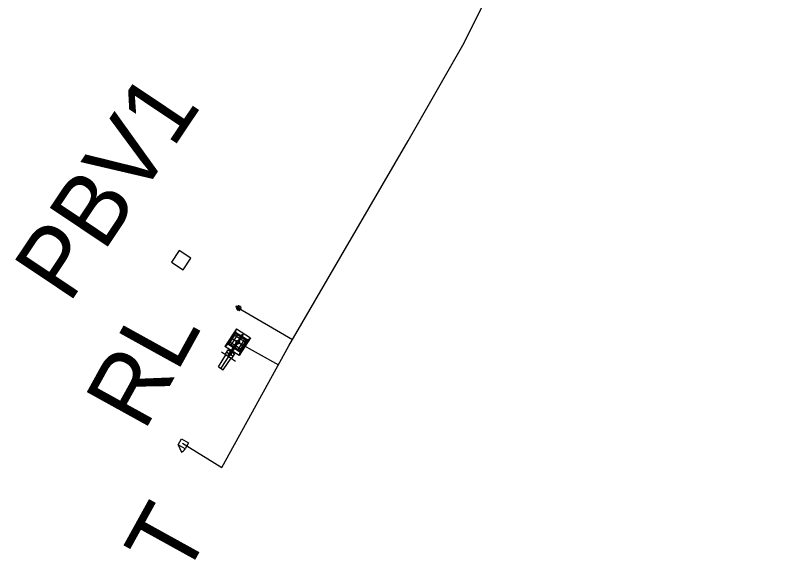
# Model space of a CAD drawing. Extents: x -717079 to -715675, y -957336 to -955099.
# Drawn here: x -715995.85 to -715968.61, y -955365.79 to -955346.3 of the extents above; entities that cross this region are included whole.
import ezdxf

# ---------------------------------------------------------------- set-up
doc = ezdxf.new("R2010")
doc.units = 0
doc.layers.add('TZ_ostatní', color=7, linetype='Continuous')

msp = doc.modelspace()

# ---------------------------------------------------------------- linework, layer by layer
at = {"layer": 'TZ_ostatní'}
for p, q in [((-715989.979, -955354.719), (-715990.252, -955355.138)), ((-715989.56, -955354.992), (-715989.979, -955354.719)), ((-715989.833, -955355.411), (-715989.56, -955354.992)), ((-715990.252, -955355.138), (-715989.833, -955355.411)), ((-715987.942, -955356.707), (-715987.953, -955356.724)), ((-715987.953, -955356.724), (-715987.902, -955356.756)), ((-715987.947, -955356.715), (-715987.788, -955356.819)), ((-715987.891, -955356.74), (-715987.942, -955356.707)), ((-715987.864, -955356.698), (-715987.93, -955356.798)), ((-715987.889, -955356.855), (-715987.796, -955356.712)), ((-715987.82, -955356.721), (-715987.857, -955356.696)), ((-715987.81, -955356.715), (-715987.813, -955356.719)), ((-715987.81, -955356.715), (-715987.793, -955356.726)), ((-715987.793, -955356.726), (-715987.796, -955356.73)), ((-715987.757, -955356.762), (-715987.794, -955356.737)), ((-715987.891, -955356.83), (-715987.928, -955356.805)), ((-715987.892, -955356.841), (-715987.889, -955356.837)), ((-715987.892, -955356.841), (-715987.875, -955356.852)), ((-715987.875, -955356.852), (-715987.872, -955356.848)), ((-715987.828, -955356.871), (-715987.865, -955356.846)), ((-715987.821, -955356.869), (-715987.755, -955356.769)), ((-715987.931, -955357.52), (-715988.338, -955358.15)), ((-715987.96, -955357.638), (-715987.931, -955357.52)), ((-715987.931, -955357.52), (-715987.427, -955357.845)), ((-715988.242, -955358.075), (-715987.96, -955357.638)), ((-715988.186, -955358.063), (-715987.948, -955357.694)), ((-715987.9, -955357.748), (-715988.117, -955358.084)), ((-715987.679, -955357.682), (-715988.086, -955358.313)), ((-715987.969, -955357.763), (-715987.633, -955357.98)), ((-715987.96, -955357.638), (-715987.775, -955357.757)), ((-715987.948, -955357.694), (-715987.96, -955357.638)), ((-715987.948, -955357.694), (-715987.793, -955357.793)), ((-715987.727, -955357.72), (-715987.859, -955357.924)), ((-715987.775, -955357.757), (-715987.859, -955357.924)), ((-715987.694, -955357.742), (-715987.825, -955357.945)), ((-715987.708, -955357.801), (-715987.825, -955357.945)), ((-715987.775, -955357.757), (-715987.727, -955357.72)), ((-715987.733, -955357.832), (-715987.578, -955357.932)), ((-715987.727, -955357.72), (-715987.694, -955357.742)), ((-715987.708, -955357.801), (-715987.694, -955357.742)), ((-715987.708, -955357.801), (-715987.523, -955357.92)), ((-715988.338, -955358.15), (-715988.242, -955358.075)), ((-715988.242, -955358.075), (-715988.186, -955358.063)), ((-715988.055, -955358.192), (-715988.242, -955358.075)), ((-715987.846, -955357.942), (-715988.189, -955358.473)), ((-715988.032, -955358.163), (-715988.186, -955358.063)), ((-715988.165, -955358.381), (-715987.94, -955358.031)), ((-715988.135, -955357.835), (-715987.63, -955358.16)), ((-715988.132, -955358.015), (-715987.796, -955358.232)), ((-715988.115, -955358.413), (-715987.889, -955358.064)), ((-715988.071, -955358.254), (-715987.94, -955358.05)), ((-715988.057, -955358.194), (-715987.94, -955358.05)), ((-715988.038, -955358.275), (-715987.906, -955358.072)), ((-715987.99, -955358.238), (-715987.906, -955358.072)), ((-715987.94, -955358.05), (-715987.906, -955358.072)), ((-715987.938, -955357.962), (-715987.826, -955358.034)), ((-715987.648, -955357.911), (-715987.865, -955358.247)), ((-715987.859, -955357.924), (-715987.825, -955357.945)), ((-715987.427, -955357.845), (-715987.833, -955358.475)), ((-715987.578, -955357.932), (-715987.817, -955358.302)), ((-715987.523, -955357.92), (-715987.805, -955358.357)), ((-715987.578, -955357.932), (-715987.523, -955357.92)), ((-715987.523, -955357.92), (-715987.427, -955357.845)), ((-715988.107, -955358.346), (-715988.487, -955358.935)), ((-715988.468, -955358.352), (-715987.963, -955358.677)), ((-715987.833, -955358.475), (-715988.338, -955358.15)), ((-715988.329, -955358.441), (-715988.221, -955358.273)), ((-715988.275, -955358.357), (-715988.048, -955358.504)), ((-715988.221, -955358.273), (-715987.994, -955358.42)), ((-715988.057, -955358.194), (-715988.071, -955358.254)), ((-715988.071, -955358.254), (-715988.038, -955358.275)), ((-715987.99, -955358.238), (-715988.038, -955358.275)), ((-715987.805, -955358.357), (-715987.99, -955358.238)), ((-715987.817, -955358.302), (-715987.972, -955358.202)), ((-715987.805, -955358.357), (-715987.833, -955358.475)), ((-715987.817, -955358.302), (-715987.805, -955358.357)), ((-715988.566, -955358.883), (-715988.312, -955358.452)), ((-715988.407, -955358.986), (-715988.119, -955358.577)), ((-715988.102, -955358.588), (-715988.329, -955358.441)), ((-715988.203, -955358.403), (-715988.119, -955358.458)), ((-715987.994, -955358.42), (-715988.102, -955358.588)), ((-715988.566, -955358.883), (-715988.407, -955358.986))]:
    msp.add_line(p, q, dxfattribs=at)
for points in [[(-715989.856, -955361.61), (-715988.453, -955362.485), (-715986.048, -955358.131), (-715981.783, -955350.799), (-715979.769, -955347.287), (-715977.617, -955342.923), (-715976.629, -955341.291), (-715976.131, -955340.684), (-715973.849, -955336.454), (-715972.108, -955333.914), (-715970.466, -955332.107), (-715968.615, -955329.738), (-715969.202, -955329.322)], [(-715989.56, -955354.992), (-715989.979, -955354.719), (-715990.252, -955355.138), (-715989.833, -955355.411), (-715989.56, -955354.992)], [(-715987.868, -955356.767), (-715985.915, -955357.903)], [(-715987.882, -955357.998), (-715986.42, -955358.806)], [(-715990.017, -955361.672), (-715989.898, -955361.463), (-715989.646, -955361.608), (-715989.766, -955361.816), (-715990.017, -955361.672)], [(-715990.017, -955361.672), (-715989.894, -955361.934)]]:
    msp.add_lwpolyline(points, dxfattribs=at)
for centre, radius in [((-715987.802, -955356.721), 0.00325), ((-715987.883, -955356.846), 0.00325), ((-715987.927, -955357.79), 0.0135), ((-715988.09, -955358.042), 0.0135), ((-715987.882, -955357.998), 0.0665), ((-715987.675, -955357.953), 0.0135), ((-715987.838, -955358.205), 0.0135), ((-715988.161, -955358.43), 0.05), ((-715988.161, -955358.43), 0.05)]:
    msp.add_circle(centre, radius, dxfattribs=at)
for centre, radius, start, end in [((-715987.86, -955356.7), 0.005, 56.9154, 146.9154), ((-715987.817, -955356.717), 0.005, 236.9154, 326.9154), ((-715987.802, -955356.721), 0.01, 326.9154, 146.9154), ((-715987.792, -955356.733), 0.005, 146.9154, 236.9154), ((-715987.926, -955356.801), 0.005, 146.9154, 236.9154), ((-715987.883, -955356.846), 0.01, 146.9154, 326.9154), ((-715987.893, -955356.834), 0.005, 326.9154, 56.9154), ((-715987.868, -955356.85), 0.005, 56.9154, 146.9154), ((-715987.825, -955356.867), 0.005, 236.9154, 326.9154), ((-715987.759, -955356.766), 0.005, 326.9154, 56.9154), ((-715990.017, -955361.672), 0.29, 295.1195, 330.1223)]:
    msp.add_arc(centre, radius, start, end, dxfattribs=at)

# ---------------------------------------------------------------- texts
for s, height, rotation, p in [('PBV1', 2.5, 56.2524, (-715993.923, -955356.661)), ('KSL', 0.02, 56.9154, (-715987.819, -955356.83)), ('RL', 2.5, 61.0784, (-715991.232, -955361.235)), ('TIZ', 0.02, 327.1899, (-715987.687, -955357.713)), ('T', 2.5, 61.0784, (-715989.821, -955366.546))]:
    msp.add_text(s, height=height, rotation=rotation, dxfattribs=at).set_placement(p)

doc.saveas('drawing.dxf')
